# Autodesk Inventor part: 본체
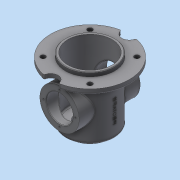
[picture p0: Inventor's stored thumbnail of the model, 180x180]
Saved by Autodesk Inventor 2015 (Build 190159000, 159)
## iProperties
Created: 2018-04
Part Number: 본체
Material: 일반
Document SubType Name: Modeling
Designer: SCD-A03
Density: 1 g/cm^3
Appearance: 기본값
Author: SCD-A03
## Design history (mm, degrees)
sketch "스케치1"
  geometry: C1 r 50 at (0, 0); 1 further point
  constraints: 1 centre point, 1 coincident
  dimensions: "d0" = 100 diameter of C1
extrude "돌출1" new body sketch "스케치1" distance "d1" = 128; taper "d2" = 0 deg
feature "쉘1" dims "d3" = 5
sketch "스케치2"
  geometry: C1 r 50 at (0, 0) reference; C2 r 40 at (0, 0)
  constraints: 1 centre point, 1 coincident
  dimensions: "d4" = 80 diameter of C2
extrude "돌출2" join sketch "스케치2" distance "d5" = 5; taper "d6" = 0 deg
sketch "스케치3"
  geometry: C1 r 50 at (0, 0) reference; C2 r 50 at (0, 0)
  constraints: 1 centre point, 1 coincident
  dimensions: "d7" = 100 diameter of C2
extrude "돌출3" join sketch "스케치3" distance "d8" = 8; taper "d9" = 0 deg
node "작업 평면1"
sketch "스케치4"
  geometry: C1 r 80 at (0, 0); C2 r 50 at (0, 0) reference; 1 further point
  constraints: 1 centre point, 1 coincident
  dimensions: "d11" = 160 diameter of C1
extrude "돌출4" join sketch "스케치4" distance "d12" = 10; taper "d13" = 0 deg
sketch "스케치5"
  geometry: C1 r 40 at (0, 0) reference; C2 r 27 at (0, 0)
  constraints: 1 centre point, 1 coincident
  dimensions: "d14" = 54 diameter of C2
extrude "돌출5" cut sketch "스케치5" stored distance "d15" = 10; taper "d16" = 0 deg
node "작업 평면2"
sketch "스케치6"
  geometry: L1 (-80, 120)-(80, 120) reference; L2 (0, 120)-(0, 60); C1 r 40 at (0, 60); 1 further point
  constraints: 2 end point, 1 centre point, 1 coincident, 1 midpoint, 1 vertical
  dimensions: "d18" = 60 distance of L2.start L2.end; "d19" = 80 diameter of C1
extrude "돌출6" join sketch "스케치6" stored distance "d20" = 10; taper "d21" = 0 deg
sketch "스케치7"
  geometry: C1 r 40 at (0, 0) reference; C2 r 27 at (0, 0); 1 further point
  constraints: 1 centre point, 1 coincident
  dimensions: "d22" = 54 diameter of C2
extrude "돌출7" cut sketch "스케치7" stored distance "d23" = 10; taper "d24" = 0 deg
sketch "스케치8" dims "d25" = 65
  geometry: L1 (-27, -52)-(27, -52) reference; L2 (-40, -65)-(40, -65) reference; L3 (-50, 50)-(50, 50) reference; L4 (-50, -60)-(50, -60) reference; C1 r 40 at (0, 0) reference; 7 further points
  constraints: 1 coincident, 1 vertical alignment, 8 other
  dimensions: "d28" = 360 deg dimension on point (0, 0) point (0, -32.5) (derived); "d30" = 52 distance from line of point (32.5, 0) L1
hole "구멍1" sketch "스케치8" at (0, -32.5), (32.5, 0), (0, 32.5), (-32.5, 0) diameter "d31" = 3.459; stored, may be unused: countersink angle "d35" = 90 deg, drill point angle "d37" = 118 deg; dims "d32" = 8, "d33" = 4, "d34" = 2, "d36" = 10
sketch "스케치9" dims "d38" = 65
  geometry: L1 (27, -62)-(27, -36) reference; C1 r 40 at (0, 0) reference; C2 r 80 at (0, 0) reference; C3 r 50 at (0, 0) reference; C4 r 80 at (0, 0) reference; 5 further points
  constraints: 1 coincident, 1 horizontal alignment, 7 other
  dimensions: "d41" = 360 deg dimension on point (0, 0) point (32.5, 0) (derived); "d43" = 5.5 distance from line of point (32.5, 0) L1
hole "구멍2" sketch "스케치9" at (32.5, 0), (0, 32.5), (-32.5, 0), (0, -32.5) diameter "d44" = 3.459; stored, may be unused: countersink angle "d48" = 90 deg, drill point angle "d50" = 118 deg; dims "d45" = 8, "d46" = 4, "d47" = 2, "d49" = 10
sketch "스케치10" dims "d52" = 135
  geometry: L1 (0, 0)-(0, -108.302); L2 (0, 0)-(95.068, -95.068); L3 (27, -62)-(-27, -62) reference; L4 (-40, -62)-(40, -62) reference; L5 (1.73, -62)-(-1.73, -62) reference; C1 r 50 at (0, 0) reference; C2 r 80 at (0, 0) reference; C3 r 1.73 at (-32.5, 0) reference; C4 r 1.73 at (32.5, 0) reference; C5 r 1.73 at (0, 32.5) reference; C6 r 1.73 at (0, -32.5) reference; C7 r 27 at (0, 0) reference; C8 r 40 at (0, 0) reference; C9 r 50 at (0, 0) reference; C10 r 80 at (0, 0) reference; C11 r 40 at (0, 0) reference; C12 r 50 at (0, 0) reference; C13 r 40 at (0, 0) reference; C14 r 1.73 at (0, -32.5) reference; C15 r 1.73 at (-32.5, 0) reference; C16 r 1.73 at (0, 32.5) reference; C17 r 1.73 at (32.5, 0) reference; C18 r 27 at (0, 0) reference; C19 r 50 at (0, 0) reference; 5 further points
  constraints: 4 end point, 1 coincident, 1 point on line, 1 vertical, 8 other
  dimensions: "d51" = 45 deg angle of L1 L2; "d55" = 360 deg dimension on point (0, 0) point (47.73, -47.73) (derived); "d57" = 33.06806 distance from line of L2.end L3; "d58" = 46.30152 distance from line of L1.end L3
hole "구멍3" sketch "스케치10" at (47.73, -47.73), (47.73, 47.73), (-47.73, 47.73), (-47.73, -47.73) diameter "d59" = 10; stored, may be unused: countersink angle "d63" = 90 deg, drill point angle "d65" = 118 deg; dims "d60" = 10, "d61" = 4, "d62" = 2, "d64" = 10
sketch "스케치11"
  geometry: C1 r 15 at (0, -80)
  constraints: 1 centre point
  dimensions: "d66" = 30 diameter of C1
extrude "돌출8" cut sketch "스케치11" stored distance "d68" = 10; taper "d69" = 0 deg
node "작업 평면3"
sketch "스케치12" dims "d11" = 160
  geometry: L1 (-78.594, 120)-(78.594, 120) reference; L2 (45, 8)-(45, 128) reference; L3 (-50, 0)-(-50, 110) reference; 2 further points
  constraints: 1 other
  dimensions: "d74" = 70 distance from line of L1 point (0, 50); "d76" = 45 distance from line of point (0, 50) L2
feature "엠보싱1" sketch "스케치12" dims "d77" = 0.5, "d78" = 0
chamfer "모따기1" distance "d79" = 1; stored, may be unused: second distance "d80" = 2, angle "d81" = 45 deg
fillet "모깎기1" dims "d82" = 5, "d83" = 3
node "솔리드1"
mirror "대칭1"
node "투영된 루프1"
node "투영된 루프2"
node "투영된 루프3"
node "투영된 루프4"
node "투영된 루프5"
other parameters: "d10" = -8, "d17" = -62
